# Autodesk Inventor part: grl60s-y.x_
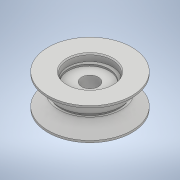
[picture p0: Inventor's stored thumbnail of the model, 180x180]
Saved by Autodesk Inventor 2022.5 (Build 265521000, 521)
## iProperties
Created: 2020-01
Part Number: grl60s-y.x_
Material: 一般
Document SubType Name: Modeling
Designer: ImaoCorp
Density: 1 g/cm^3
Appearance: 既定
Sending System: SOLIDWORKS 2018-2018316
MC: AMD64
MC_MODEL: Intel64 Family 6 Model 60 Stepping 3, GenuineIntel
OS: Windows_NT
FRU: Parasolid Version 30.0, build 310,  6- 8-2018
FORMAT: text
GUISE: transmit
KEY: grl60s-y
FILE: grl60s-y.x_t
DATE: Thu Jan 23 16:41:31 2020
Author: ImaoCorp
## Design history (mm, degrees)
feature "Base1"
node "ソリッド1"
